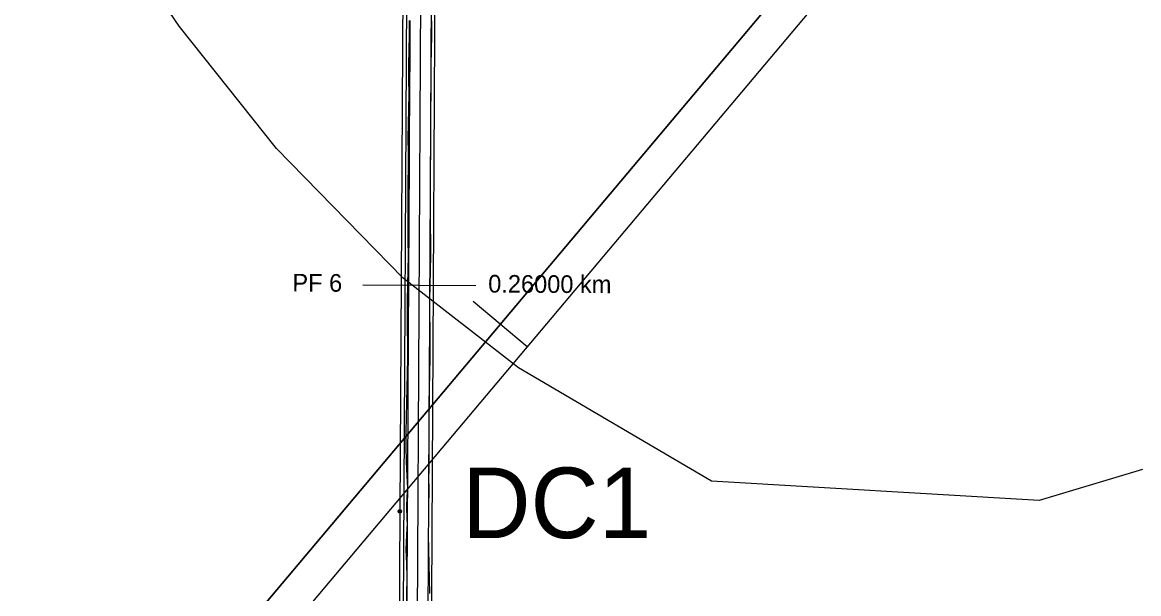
# Model space of a CAD drawing. Extents: x -555887 to -552101, y -1100251 to -1096546.
# Drawn here: x -554592.1 to -554433.8, y -1097475.3 to -1097394.3 of the extents above; entities that cross this region are included whole.
import ezdxf

# ---------------------------------------------------------------- set-up
doc = ezdxf.new("R2010")
doc.units = 0
for name, color, linetype in [('07_ELEKTRO', 7, 'Continuous'), ('PARCELY_cesty', 7, 'Continuous'), ('POLYGONY_POPIS_CESTY', 7, 'Continuous'), ('POLYGONY_SITUACE_PF', 7, 'Continuous'), ('POLYGONY_SITUACE_PF_POPISY', 7, 'Continuous'), ('POLYGONY_SITUACE_PO', 7, 'Continuous'), ('ram_VC2', 7, 'Continuous'), ('vrstevnice', 7, 'Continuous'), ('ZSST', 7, 'Continuous')]:
    doc.layers.add(name, color=color, linetype=linetype)

msp = doc.modelspace()

# ---------------------------------------------------------------- linework, layer by layer
at = {"layer": '07_ELEKTRO'}
msp.add_lwpolyline([(-554536.82, -1097177.88), (-554537.6, -1097278.41), (-554538.02, -1097373.3), (-554538.57, -1097463.61), (-554539.13, -1097565.86), (-554539.54, -1097665.45), (-554540.25, -1097764.02), (-554540.7, -1097863.05), (-554541.19, -1097956), (-554541.54, -1098055.43), (-554541.8, -1098155.57), (-554542, -1098255.51), (-554542.34, -1098356.72), (-554542.76, -1098456.4)], dxfattribs=at)
at = {"layer": 'PARCELY_cesty'}
for points in [[(-554512.1, -1097673.16), (-554518.74, -1097666.22), (-554524.72, -1097658.67), (-554527.98, -1097653.27), (-554531.84, -1097644.51), (-554533.52, -1097638.42), (-554534.52, -1097632.14), (-554534.84, -1097625.74), (-554532.6, -1097210.77)], [(-554515.01, -1097675.92), (-554521.76, -1097668.85), (-554528.02, -1097660.96), (-554531.54, -1097655.12), (-554535.62, -1097645.85), (-554537.43, -1097639.27), (-554538.51, -1097632.56), (-554538.84, -1097625.83), (-554536.72, -1097234.2)]]:
    msp.add_lwpolyline(points, dxfattribs=at)
at = {"layer": 'POLYGONY_SITUACE_PF'}
for p, q in [((-554543.79, -1097431.49), (-554535.79, -1097431.53)), ((-554535.79, -1097431.53), (-554527.79, -1097431.58))]:
    msp.add_line(p, q, dxfattribs=at)
at = {"layer": 'POLYGONY_SITUACE_PO'}
for p, q in [((-554536.84, -1097625.79), (-554534.58, -1097207.13)), ((-554534.46, -1097462.79), (-554533.1, -1097212.13)), ((-554537.21, -1097396.11), (-554537.19, -1097394.03)), ((-554537.1, -1097396.11), (-554537.09, -1097394.03)), ((-554534.1, -1097396.13), (-554534.09, -1097394.04)), ((-554534.03, -1097396.13), (-554534.01, -1097394.04)), ((-554537.24, -1097398.19), (-554537.21, -1097396.11)), ((-554537.11, -1097398.19), (-554537.1, -1097396.11)), ((-554534.11, -1097398.21), (-554534.1, -1097396.13)), ((-554534.08, -1097398.21), (-554534.03, -1097396.13)), ((-554537.27, -1097400.28), (-554537.24, -1097398.19)), ((-554537.12, -1097400.28), (-554537.11, -1097398.19)), ((-554534.12, -1097400.29), (-554534.11, -1097398.21)), ((-554534.12, -1097400.29), (-554534.08, -1097398.21)), ((-554537.27, -1097402.36), (-554537.27, -1097400.28)), ((-554537.13, -1097402.36), (-554537.12, -1097400.28)), ((-554534.13, -1097402.38), (-554534.12, -1097400.29)), ((-554534.12, -1097402.38), (-554534.12, -1097400.29)), ((-554537.26, -1097404.44), (-554537.27, -1097402.36)), ((-554537.14, -1097404.44), (-554537.13, -1097402.36)), ((-554534.14, -1097404.46), (-554534.13, -1097402.38)), ((-554534.12, -1097404.46), (-554534.12, -1097402.38)), ((-554537.3, -1097406.53), (-554537.26, -1097404.44)), ((-554537.15, -1097406.53), (-554537.14, -1097404.44)), ((-554534.15, -1097406.54), (-554534.14, -1097404.46)), ((-554534.15, -1097406.54), (-554534.12, -1097404.46)), ((-554537.35, -1097408.61), (-554537.3, -1097406.53)), ((-554537.17, -1097408.61), (-554537.15, -1097406.53)), ((-554534.17, -1097408.63), (-554534.15, -1097406.54)), ((-554534.17, -1097408.63), (-554534.15, -1097406.54)), ((-554534.15, -1097406.54), (-554534.15, -1097406.54)), ((-554537.38, -1097410.69), (-554537.35, -1097408.61)), ((-554537.18, -1097410.69), (-554537.17, -1097408.61)), ((-554534.18, -1097410.71), (-554534.17, -1097408.63)), ((-554534.18, -1097410.71), (-554534.17, -1097408.63)), ((-554537.33, -1097412.78), (-554537.38, -1097410.69)), ((-554537.19, -1097412.78), (-554537.18, -1097410.69)), ((-554534.19, -1097412.79), (-554534.18, -1097410.71)), ((-554534.19, -1097412.79), (-554534.18, -1097410.71)), ((-554537.34, -1097414.86), (-554537.33, -1097412.78)), ((-554537.2, -1097414.86), (-554537.19, -1097412.78)), ((-554534.2, -1097414.88), (-554534.19, -1097412.79)), ((-554534.2, -1097414.88), (-554534.19, -1097412.79)), ((-554537.36, -1097416.94), (-554537.34, -1097414.86)), ((-554537.21, -1097416.94), (-554537.2, -1097414.86)), ((-554534.21, -1097416.96), (-554534.2, -1097414.88)), ((-554534.21, -1097416.96), (-554534.2, -1097414.88)), ((-554537.38, -1097419.03), (-554537.36, -1097416.94)), ((-554537.22, -1097419.03), (-554537.21, -1097416.94)), ((-554534.22, -1097419.04), (-554534.21, -1097416.96)), ((-554534.22, -1097419.04), (-554534.21, -1097416.96)), ((-554534.21, -1097416.96), (-554534.21, -1097416.96)), ((-554537.4, -1097421.11), (-554537.38, -1097419.03)), ((-554537.23, -1097421.11), (-554537.22, -1097419.03)), ((-554534.23, -1097421.13), (-554534.22, -1097419.04)), ((-554534.22, -1097421.13), (-554534.22, -1097419.04)), ((-554537.39, -1097423.19), (-554537.4, -1097421.11)), ((-554537.24, -1097423.19), (-554537.23, -1097421.11)), ((-554534.24, -1097423.21), (-554534.23, -1097421.13)), ((-554534.21, -1097423.21), (-554534.22, -1097421.13)), ((-554537.37, -1097425.28), (-554537.39, -1097423.19)), ((-554537.26, -1097425.28), (-554537.24, -1097423.19)), ((-554534.26, -1097425.29), (-554534.24, -1097423.21)), ((-554534.19, -1097425.29), (-554534.21, -1097423.21)), ((-554537.34, -1097427.36), (-554537.37, -1097425.28)), ((-554537.27, -1097427.36), (-554537.26, -1097425.28)), ((-554534.27, -1097427.38), (-554534.26, -1097425.29)), ((-554534.17, -1097427.38), (-554534.19, -1097425.29)), ((-554537.36, -1097429.44), (-554537.34, -1097427.36)), ((-554537.28, -1097429.44), (-554537.27, -1097427.36)), ((-554534.28, -1097429.46), (-554534.27, -1097427.38)), ((-554534.21, -1097429.46), (-554534.17, -1097427.38)), ((-554537.41, -1097431.53), (-554537.36, -1097429.44)), ((-554537.29, -1097431.53), (-554537.28, -1097429.44)), ((-554534.29, -1097431.54), (-554534.28, -1097429.46)), ((-554534.27, -1097431.54), (-554534.21, -1097429.46)), ((-554537.46, -1097433.61), (-554537.41, -1097431.53)), ((-554537.3, -1097433.61), (-554537.29, -1097431.53)), ((-554534.3, -1097433.63), (-554534.29, -1097431.54)), ((-554534.3, -1097433.63), (-554534.27, -1097431.54)), ((-554537.48, -1097435.69), (-554537.46, -1097433.61)), ((-554537.31, -1097435.69), (-554537.3, -1097433.61)), ((-554534.31, -1097435.71), (-554534.3, -1097433.63)), ((-554534.31, -1097435.71), (-554534.3, -1097433.63)), ((-554537.48, -1097437.77), (-554537.48, -1097435.69)), ((-554537.32, -1097437.78), (-554537.31, -1097435.69)), ((-554534.32, -1097437.79), (-554534.31, -1097435.71)), ((-554534.28, -1097437.79), (-554534.31, -1097435.71)), ((-554537.41, -1097439.86), (-554537.48, -1097437.77)), ((-554537.33, -1097439.86), (-554537.32, -1097437.78)), ((-554534.33, -1097439.88), (-554534.32, -1097437.79)), ((-554534.24, -1097439.88), (-554534.28, -1097437.79)), ((-554537.44, -1097441.94), (-554537.41, -1097439.86)), ((-554537.35, -1097441.94), (-554537.33, -1097439.86)), ((-554534.35, -1097441.96), (-554534.33, -1097439.88)), ((-554534.28, -1097441.96), (-554534.24, -1097439.88)), ((-554537.48, -1097444.02), (-554537.44, -1097441.94)), ((-554537.36, -1097444.03), (-554537.35, -1097441.94)), ((-554534.36, -1097444.04), (-554534.35, -1097441.96)), ((-554534.32, -1097444.04), (-554534.28, -1097441.96)), ((-554537.52, -1097446.11), (-554537.48, -1097444.02)), ((-554537.37, -1097446.11), (-554537.36, -1097444.03)), ((-554534.37, -1097446.13), (-554534.36, -1097444.04)), ((-554534.36, -1097446.13), (-554534.32, -1097444.04)), ((-554537.57, -1097448.19), (-554537.52, -1097446.11)), ((-554537.38, -1097448.19), (-554537.37, -1097446.11)), ((-554534.38, -1097448.21), (-554534.37, -1097446.13)), ((-554534.38, -1097448.21), (-554534.36, -1097446.13)), ((-554537.61, -1097450.27), (-554537.57, -1097448.19)), ((-554537.39, -1097450.28), (-554537.38, -1097448.19)), ((-554534.39, -1097450.29), (-554534.38, -1097448.21)), ((-554534.39, -1097450.29), (-554534.38, -1097448.21)), ((-554534.38, -1097448.21), (-554534.38, -1097448.21)), ((-554537.64, -1097452.36), (-554537.61, -1097450.27)), ((-554537.4, -1097452.36), (-554537.39, -1097450.28)), ((-554534.4, -1097452.38), (-554534.39, -1097450.29)), ((-554534.4, -1097452.38), (-554534.39, -1097450.29)), ((-554537.64, -1097454.44), (-554537.64, -1097452.36)), ((-554537.41, -1097454.44), (-554537.4, -1097452.36)), ((-554534.41, -1097454.46), (-554534.4, -1097452.38)), ((-554534.41, -1097454.46), (-554534.4, -1097452.38)), ((-554537.62, -1097456.52), (-554537.64, -1097454.44)), ((-554537.43, -1097456.53), (-554537.41, -1097454.44)), ((-554534.43, -1097456.54), (-554534.41, -1097454.46)), ((-554534.43, -1097456.54), (-554534.41, -1097454.46)), ((-554537.51, -1097458.61), (-554537.62, -1097456.52)), ((-554537.44, -1097458.61), (-554537.43, -1097456.53)), ((-554534.44, -1097458.62), (-554534.43, -1097456.54)), ((-554534.44, -1097458.62), (-554534.43, -1097456.54)), ((-554537.45, -1097460.3), (-554537.51, -1097458.61)), ((-554537.45, -1097460.69), (-554537.44, -1097458.61)), ((-554534.45, -1097460.71), (-554534.44, -1097458.62)), ((-554534.42, -1097460.71), (-554534.44, -1097458.62)), ((-554534.44, -1097458.62), (-554534.44, -1097458.62)), ((-554537.47, -1097460.69), (-554537.45, -1097460.3)), ((-554537.56, -1097462.77), (-554537.47, -1097460.69)), ((-554537.46, -1097462.78), (-554537.45, -1097460.69)), ((-554534.46, -1097462.79), (-554534.45, -1097460.71)), ((-554534.46, -1097462.79), (-554534.42, -1097460.71)), ((-554537.5, -1097464.86), (-554537.56, -1097462.77)), ((-554537.47, -1097464.86), (-554537.46, -1097462.78)), ((-554534.47, -1097464.87), (-554534.46, -1097462.79)), ((-554534.47, -1097464.87), (-554534.46, -1097462.79)), ((-554534.47, -1097464.87), (-554534.46, -1097462.79)), ((-554534.46, -1097462.79), (-554534.46, -1097462.79)), ((-554537.47, -1097465.33), (-554537.5, -1097464.86)), ((-554537.48, -1097466.94), (-554537.47, -1097464.86)), ((-554534.48, -1097466.96), (-554534.47, -1097464.87)), ((-554534.48, -1097466.96), (-554534.47, -1097464.87)), ((-554534.48, -1097466.96), (-554534.47, -1097464.87)), ((-554537.57, -1097466.94), (-554537.47, -1097465.33)), ((-554537.65, -1097469.02), (-554537.57, -1097466.94)), ((-554537.49, -1097469.03), (-554537.48, -1097466.94)), ((-554534.49, -1097469.04), (-554534.48, -1097466.96)), ((-554534.49, -1097469.04), (-554534.48, -1097466.96)), ((-554534.45, -1097469.04), (-554534.48, -1097466.96)), ((-554534.48, -1097466.96), (-554534.48, -1097466.96)), ((-554537.56, -1097471.11), (-554537.65, -1097469.02)), ((-554537.5, -1097471.11), (-554537.49, -1097469.03)), ((-554534.5, -1097471.12), (-554534.49, -1097469.04)), ((-554534.5, -1097471.12), (-554534.49, -1097469.04)), ((-554534.38, -1097471.13), (-554534.45, -1097469.04)), ((-554537.51, -1097472.88), (-554537.56, -1097471.11)), ((-554537.52, -1097473.19), (-554537.5, -1097471.11)), ((-554534.52, -1097473.21), (-554534.5, -1097471.12)), ((-554534.52, -1097473.21), (-554534.5, -1097471.12)), ((-554534.35, -1097473.21), (-554534.38, -1097471.13)), ((-554537.52, -1097473.19), (-554537.51, -1097472.88)), ((-554537.56, -1097475.27), (-554537.52, -1097473.19)), ((-554537.53, -1097475.28), (-554537.52, -1097473.19)), ((-554534.53, -1097475.29), (-554534.52, -1097473.21)), ((-554534.53, -1097475.29), (-554534.52, -1097473.21)), ((-554534.33, -1097475.29), (-554534.35, -1097473.21)), ((-554537.6, -1097477.36), (-554537.56, -1097475.27)), ((-554537.54, -1097477.36), (-554537.53, -1097475.28)), ((-554534.54, -1097477.37), (-554534.53, -1097475.29)), ((-554534.54, -1097477.37), (-554534.53, -1097475.29))]:
    msp.add_line(p, q, dxfattribs=at)
at = {"layer": 'ram_VC2'}
msp.add_line((-554520.51, -1097440.31), (-554528.16, -1097433.87), dxfattribs=at)
for points in [[(-554114.88, -1096958.27), (-554342.13, -1096767.04), (-555018.18, -1097570.44), (-554790.93, -1097761.67)], [(-554121.93, -1096958.88), (-554341.52, -1096774.09), (-555011.14, -1097569.84), (-554791.54, -1097754.63)]]:
    msp.add_lwpolyline(points, close=True, dxfattribs=at)
for points in [[(-554114.88, -1096958.27), (-554342.13, -1096767.04), (-555018.18, -1097570.44), (-554790.93, -1097761.67), (-554114.88, -1096958.27)], [(-554791.54, -1097754.63), (-555011.14, -1097569.84), (-554341.52, -1096774.09), (-554121.93, -1096958.88), (-554791.54, -1097754.63)]]:
    msp.add_lwpolyline(points, dxfattribs=at)
at = {"layer": 'vrstevnice'}
msp.add_lwpolyline([(-554433.29, -1097457.68), (-554447.93, -1097462.07), (-554494.36, -1097459.35), (-554521.76, -1097443.27), (-554538.07, -1097430.53), (-554556.06, -1097412.15), (-554569.86, -1097394.82), (-554589.52, -1097366)], dxfattribs=at)
at = {"layer": 'ZSST'}
msp.add_lwpolyline([(-554536.82, -1097177.88), (-554537.6, -1097278.41), (-554538.02, -1097373.3), (-554538.57, -1097463.61), (-554539.13, -1097565.86), (-554539.54, -1097665.45), (-554540.25, -1097764.02), (-554540.7, -1097863.05)], dxfattribs=at)
for radius in [0.25, 0.158, 0.05]:
    msp.add_circle((-554538.57, -1097463.61), radius, dxfattribs=at)

# ---------------------------------------------------------------- texts
at = {"layer": 'POLYGONY_POPIS_CESTY'}
msp.add_text('DC1', height=10, dxfattribs=at).set_placement((-554529.69, -1097467.41))
at = {"layer": 'POLYGONY_SITUACE_PF_POPISY'}
for s, p in [('PF 6', (-554553.8, -1097432.44)), ('0.26000 km', (-554526.04, -1097432.59))]:
    msp.add_text(s, height=2.5, rotation=359.6899, dxfattribs=at).set_placement(p)

doc.saveas('drawing.dxf')
